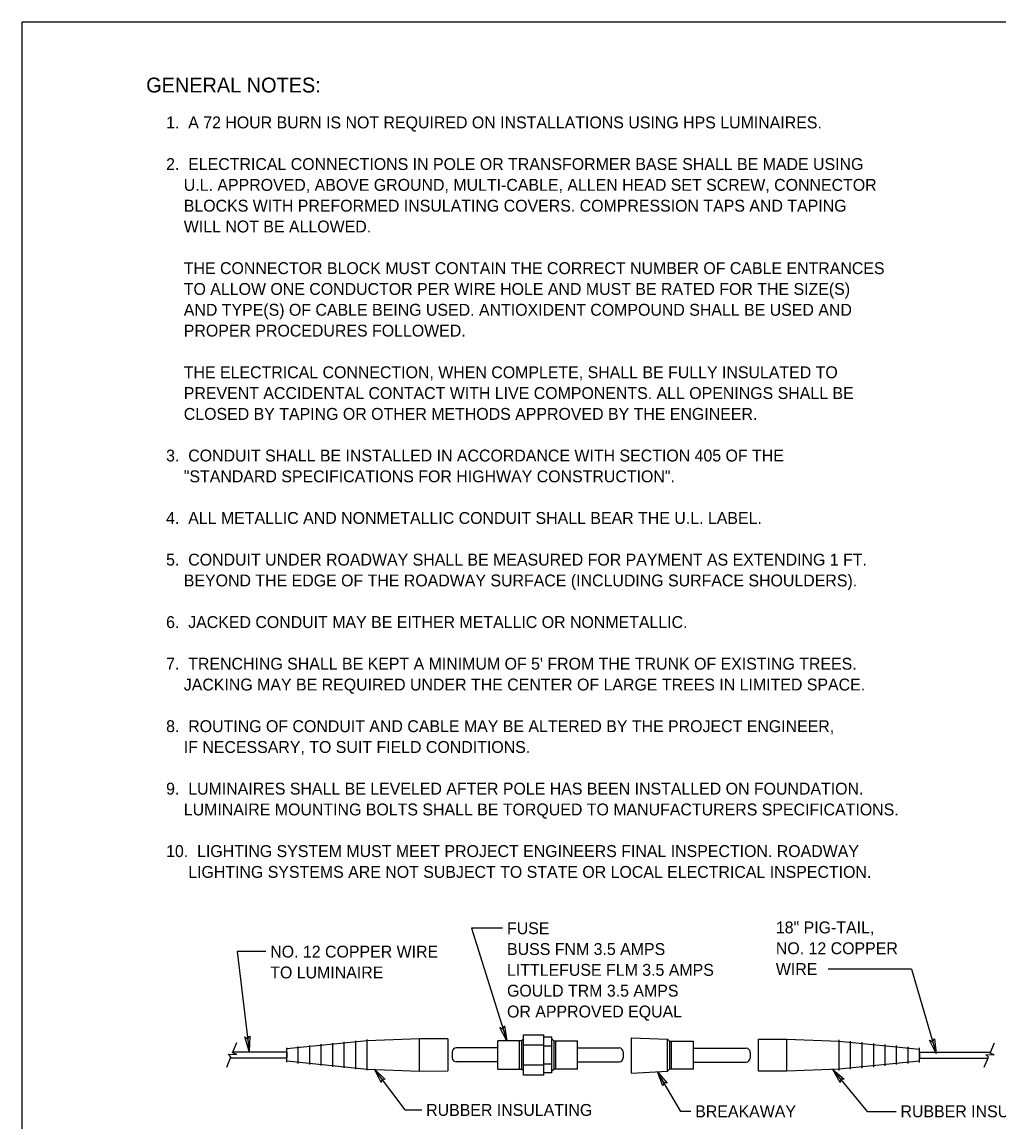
# Model space of a CAD drawing. Extents: x 99968 to 128667, y 90163 to 102182.
# Drawn here: x 125467 to 126452, y 94563 to 95672 of the extents above; entities that cross this region are included whole.
import ezdxf

# ---------------------------------------------------------------- set-up
doc = ezdxf.new("R2010")
doc.units = 0
doc.layers.add('Default', color=7, linetype='Continuous')
doc.layers.add('RD Standard Plans Active', color=7, linetype='Continuous')

msp = doc.modelspace()

# ---------------------------------------------------------------- linework, layer by layer
at = {"layer": 'Default'}
msp.add_lwpolyline([(125467.5, 95671.5), (128667.2, 95671.5), (128667.2, 93471.9), (125467.5, 93471.9)], close=True, dxfattribs=at)
at = {"layer": 'RD Standard Plans Active'}
for p, q in [((125920.9, 94757.4), (125956.5, 94643.9)), ((125952.4, 94757.4), (125920.9, 94757.4)), ((125713.5, 94733.8), (125684.5, 94733.8)), ((125684.5, 94733.8), (125696.6, 94633.5)), ((126364.9, 94716.2), (126280.8, 94716.2)), ((126364.9, 94716.2), (126389.7, 94630.9)), ((125680, 94631.7), (125684.3, 94642)), ((125815.9, 94643.8), (125734.7, 94635.7)), ((125757.9, 94620), (125757.9, 94639.2)), ((125769.5, 94618.8), (125769.5, 94640.4)), ((125781.1, 94617.7), (125781.1, 94641.6)), ((125792.7, 94616.5), (125792.7, 94642.7)), ((125804.3, 94615.4), (125804.3, 94643.9)), ((125868.7, 94645.8), (125815.9, 94643.8)), ((125815.9, 94614.2), (125815.9, 94645)), ((125897.1, 94645.9), (125868.7, 94645.8)), ((125868.7, 94613.3), (125868.7, 94645.8)), ((125897.1, 94645.9), (125897.1, 94613.4)), ((125969.5, 94643.9), (125947.5, 94643.9)), ((125947.5, 94615.4), (125947.5, 94643.8)), ((125971.6, 94643.9), (125969.5, 94643.9)), ((125969.5, 94615.4), (125969.5, 94643.9)), ((125971.6, 94643.9), (125971.5, 94615.4)), ((125971.6, 94643.9), (125973.6, 94645.9)), ((125973.6, 94609.3), (125973.6, 94649.9)), ((125973.6, 94649.9), (125993.9, 94649.9)), ((125973.6, 94613.4), (125973.6, 94645.9)), ((125973.6, 94639.8), (125993.9, 94639.8)), ((125993.9, 94609.3), (125993.9, 94649.9)), ((125993.9, 94611.4), (125993.9, 94647.9)), ((125993.9, 94647.9), (126002, 94647.9)), ((126002, 94611.4), (126002, 94647.9)), ((126004, 94643.9), (126002, 94645.9)), ((126004, 94643.9), (126006, 94643.9)), ((126004, 94643.9), (126004, 94615.4)), ((126006, 94615.4), (126006, 94643.9)), ((126006, 94643.9), (126028.1, 94643.9)), ((126028.1, 94615.4), (126028.1, 94643.8)), ((126082.3, 94646.7), (126118.8, 94645.6)), ((126082.3, 94611.1), (126082.3, 94646.7)), ((126118.8, 94613.1), (126118.8, 94645.6)), ((126120.8, 94643.6), (126118.8, 94645.6)), ((126120.8, 94643.6), (126122.9, 94643.6)), ((126120.8, 94643.6), (126120.8, 94615.2)), ((126122.9, 94615.2), (126122.9, 94643.6)), ((126122.9, 94643.6), (126144.9, 94643.6)), ((126144.9, 94615.1), (126144.9, 94643.6)), ((126210.7, 94613.1), (126210.7, 94645.6)), ((126210.7, 94645.6), (126239.2, 94645.6)), ((126239.2, 94613.1), (126239.2, 94645.6)), ((126239.2, 94645.6), (126291.9, 94643.6)), ((126291.9, 94613.9), (126291.9, 94644.8)), ((126291.9, 94643.6), (126373.1, 94635.5)), ((126303.5, 94615.1), (126303.5, 94643.6)), ((126315.2, 94616.3), (126315.2, 94642.5)), ((126326.8, 94617.4), (126326.8, 94641.3)), ((126338.3, 94618.6), (126338.3, 94640.2)), ((126444.4, 94631.5), (126448.7, 94641.8)), ((125675.7, 94630.3), (125684.1, 94629.9)), ((125678.3, 94627.7), (125675.7, 94630.3)), ((125684.1, 94629.9), (125680, 94631.7)), ((125680.3, 94632.6), (125734.7, 94632.6)), ((125734.7, 94622.3), (125734.7, 94636.9)), ((125734.7, 94632.6), (125734.7, 94626.6)), ((125734.7, 94626.6), (125734.7, 94632.6)), ((125746.3, 94621.1), (125746.3, 94638.1)), ((125901.6, 94632.6), (125901.6, 94626.6)), ((125947.5, 94636.6), (125905.6, 94636.6)), ((125993.9, 94638.8), (126002, 94638.8)), ((126028.1, 94636.6), (126070, 94636.6)), ((126074, 94632.6), (126074, 94626.6)), ((126144.9, 94636.4), (126198.1, 94636.4)), ((126202.1, 94632.4), (126202.1, 94626.4)), ((126349.9, 94619.8), (126349.9, 94639)), ((126361.6, 94620.9), (126361.6, 94637.8)), ((126373.1, 94622.1), (126373.1, 94636.7)), ((126373.1, 94632.4), (126373.1, 94626.4)), ((126373.1, 94632.4), (126444.7, 94632.4)), ((126442.7, 94627.4), (126440.1, 94630.1)), ((126440.1, 94630.1), (126448.5, 94629.7)), ((126448.5, 94629.7), (126444.4, 94631.5)), ((125674, 94617.4), (125678.3, 94627.7)), ((125677.8, 94626.6), (125734.7, 94626.6)), ((125734.7, 94623.5), (125815.9, 94615.4)), ((125947.5, 94622.6), (125905.6, 94622.6)), ((125973.6, 94619.5), (125993.9, 94619.5)), ((125993.9, 94620.5), (126002, 94620.5)), ((126028.1, 94622.6), (126070, 94622.6)), ((126144.9, 94622.4), (126198.1, 94622.4)), ((126373.1, 94623.3), (126291.9, 94615.2)), ((126373.1, 94626.4), (126442.3, 94626.4)), ((126438.4, 94617.2), (126442.7, 94627.4)), ((125815.9, 94615.4), (125868.7, 94613.3)), ((125854.2, 94574.1), (125823, 94615.1)), ((125868.7, 94613.3), (125897.1, 94613.4)), ((125947.5, 94615.4), (125969.5, 94615.4)), ((125969.5, 94615.4), (125971.5, 94615.4)), ((125973.6, 94613.4), (125971.5, 94615.4)), ((125993.9, 94609.3), (125973.6, 94609.3)), ((126002, 94611.4), (125993.9, 94611.4)), ((126002, 94613.4), (126004, 94615.4)), ((126006, 94615.4), (126004, 94615.4)), ((126028.1, 94615.4), (126006, 94615.4)), ((126082.3, 94611.1), (126118.8, 94613.1)), ((126132.3, 94572.7), (126108.6, 94612.6)), ((126118.8, 94613.1), (126120.8, 94615.2)), ((126122.9, 94615.2), (126120.8, 94615.2)), ((126144.9, 94615.1), (126122.9, 94615.2)), ((126239.2, 94613.1), (126210.7, 94613.1)), ((126291.9, 94615.2), (126239.2, 94613.1)), ((126320.5, 94572.7), (126285.5, 94614.9)), ((125854.2, 94574.1), (125870.8, 94574.1)), ((126142.3, 94572.7), (126132.3, 94572.7)), ((126320.5, 94572.7), (126349.4, 94572.7))]:
    msp.add_line(p, q, dxfattribs=at)
for points in [[(125954.4, 94658.8), (125956.5, 94643.9), (125949.6, 94657.3), (125952.7, 94655.9)], [(125697.4, 94648.6), (125696.6, 94633.5), (125692.3, 94648), (125695.1, 94646)], [(126388, 94645.9), (126389.7, 94630.9), (126383.1, 94644.5), (126386.2, 94642.9)], [(125830, 94601.7), (125823, 94615.1), (125834, 94604.8), (125830.6, 94605.1)], [(126114.1, 94598.5), (126108.6, 94612.6), (126118.4, 94601.1), (126115, 94601.8)], [(126293, 94601.8), (126285.5, 94614.9), (126296.9, 94605.1), (126293.5, 94605.2)]]:
    msp.add_lwpolyline(points, close=True, dxfattribs=at)
for centre, start, end in [((125905.6, 94632.6), 90, 180), ((126070, 94632.6), 0, 90), ((126198.1, 94632.4), 0, 90), ((125905.6, 94626.6), 180, 270), ((126070, 94626.6), 270, 360), ((126198.1, 94626.4), 270, 360)]:
    msp.add_arc(centre, 4, start, end, dxfattribs=at)

# ---------------------------------------------------------------- texts
for s, height, p in [('GENERAL NOTES:', 15, (125592.8, 95600.4)), ('1.  A 72 HOUR BURN IS NOT REQUIRED ON INSTALLATIONS USING HPS LUMINAIRES.', 12, (125612.9, 95564.2)), ('2.  ELECTRICAL CONNECTIONS IN POLE OR TRANSFORMER BASE SHALL BE MADE USING', 12, (125612.9, 95522.2)), ('    U.L. APPROVED, ABOVE GROUND, MULTI-CABLE, ALLEN HEAD SET SCREW, CONNECTOR', 12, (125612.9, 95501.2)), ('    BLOCKS WITH PREFORMED INSULATING COVERS. COMPRESSION TAPS AND TAPING', 12, (125612.9, 95480.2)), ('    WILL NOT BE ALLOWED.', 12, (125612.9, 95459.2)), ('    THE CONNECTOR BLOCK MUST CONTAIN THE CORRECT NUMBER OF CABLE ENTRANCES', 12, (125612.9, 95417.2)), ('    TO ALLOW ONE CONDUCTOR PER WIRE HOLE AND MUST BE RATED FOR THE SIZE(S)', 12, (125612.9, 95396.2)), ('    AND TYPE(S) OF CABLE BEING USED. ANTIOXIDENT COMPOUND SHALL BE USED AND', 12, (125612.9, 95375.2)), ('    PROPER PROCEDURES FOLLOWED.', 12, (125612.9, 95354.2)), ('    THE ELECTRICAL CONNECTION, WHEN COMPLETE, SHALL BE FULLY INSULATED TO', 12, (125612.9, 95312.2)), ('    PREVENT ACCIDENTAL CONTACT WITH LIVE COMPONENTS. ALL OPENINGS SHALL BE', 12, (125612.9, 95291.2)), ('    CLOSED BY TAPING OR OTHER METHODS APPROVED BY THE ENGINEER.', 12, (125612.9, 95270.2)), ('3.  CONDUIT SHALL BE INSTALLED IN ACCORDANCE WITH SECTION 405 OF THE', 12, (125612.9, 95228.2)), ('    "STANDARD SPECIFICATIONS FOR HIGHWAY CONSTRUCTION".', 12, (125612.9, 95207.2)), ('4.  ALL METALLIC AND NONMETALLIC CONDUIT SHALL BEAR THE U.L. LABEL.', 12, (125612.9, 95165.2)), ('5.  CONDUIT UNDER ROADWAY SHALL BE MEASURED FOR PAYMENT AS EXTENDING 1 FT.', 12, (125612.9, 95123.2)), ('    BEYOND THE EDGE OF THE ROADWAY SURFACE (INCLUDING SURFACE SHOULDERS).', 12, (125612.9, 95102.2)), ('6.  JACKED CONDUIT MAY BE EITHER METALLIC OR NONMETALLIC.', 12, (125612.9, 95060.2)), ("7.  TRENCHING SHALL BE KEPT A MINIMUM OF 5' FROM THE TRUNK OF EXISTING TREES.", 12, (125612.9, 95018.2)), ('    JACKING MAY BE REQUIRED UNDER THE CENTER OF LARGE TREES IN LIMITED SPACE.', 12, (125612.9, 94997.2)), ('8.  ROUTING OF CONDUIT AND CABLE MAY BE ALTERED BY THE PROJECT ENGINEER,', 12, (125612.9, 94955.2)), ('    IF NECESSARY, TO SUIT FIELD CONDITIONS.', 12, (125612.9, 94934.2)), ('9.  LUMINAIRES SHALL BE LEVELED AFTER POLE HAS BEEN INSTALLED ON FOUNDATION.', 12, (125612.9, 94892.2)), ('    LUMINAIRE MOUNTING BOLTS SHALL BE TORQUED TO MANUFACTURERS SPECIFICATIONS.', 12, (125612.9, 94871.2)), ('10.  LIGHTING SYSTEM MUST MEET PROJECT ENGINEERS FINAL INSPECTION. ROADWAY', 12, (125612.9, 94829.2)), ('     LIGHTING SYSTEMS ARE NOT SUBJECT TO STATE OR LOCAL ELECTRICAL INSPECTION.', 12, (125612.9, 94808.2)), (' FUSE', 12, (125952.4, 94751.4)), ('18" PIG-TAIL,', 12, (126228.1, 94752.2)), (' NO. 12 COPPER WIRE', 12, (125713.5, 94727.8)), (' BUSS FNM 3.5 AMPS', 12, (125952.4, 94730.4)), ('NO. 12 COPPER', 12, (126228.1, 94731.2)), (' TO LUMINAIRE', 12, (125713.5, 94706.8)), (' LITTLEFUSE FLM 3.5 AMPS', 12, (125952.4, 94709.4)), ('WIRE ', 12, (126228.1, 94710.2)), (' GOULD TRM 3.5 AMPS', 12, (125952.4, 94688.4)), (' OR APPROVED EQUAL', 12, (125952.4, 94667.4)), (' RUBBER INSULATING', 12, (125870.8, 94568.1)), (' BREAKAWAY', 12, (126142.3, 94566.7)), (' RUBBER INSULATING', 12, (126349.4, 94566.7))]:
    msp.add_text(s, height=height, dxfattribs=at).set_placement(p)

doc.saveas('drawing.dxf')
